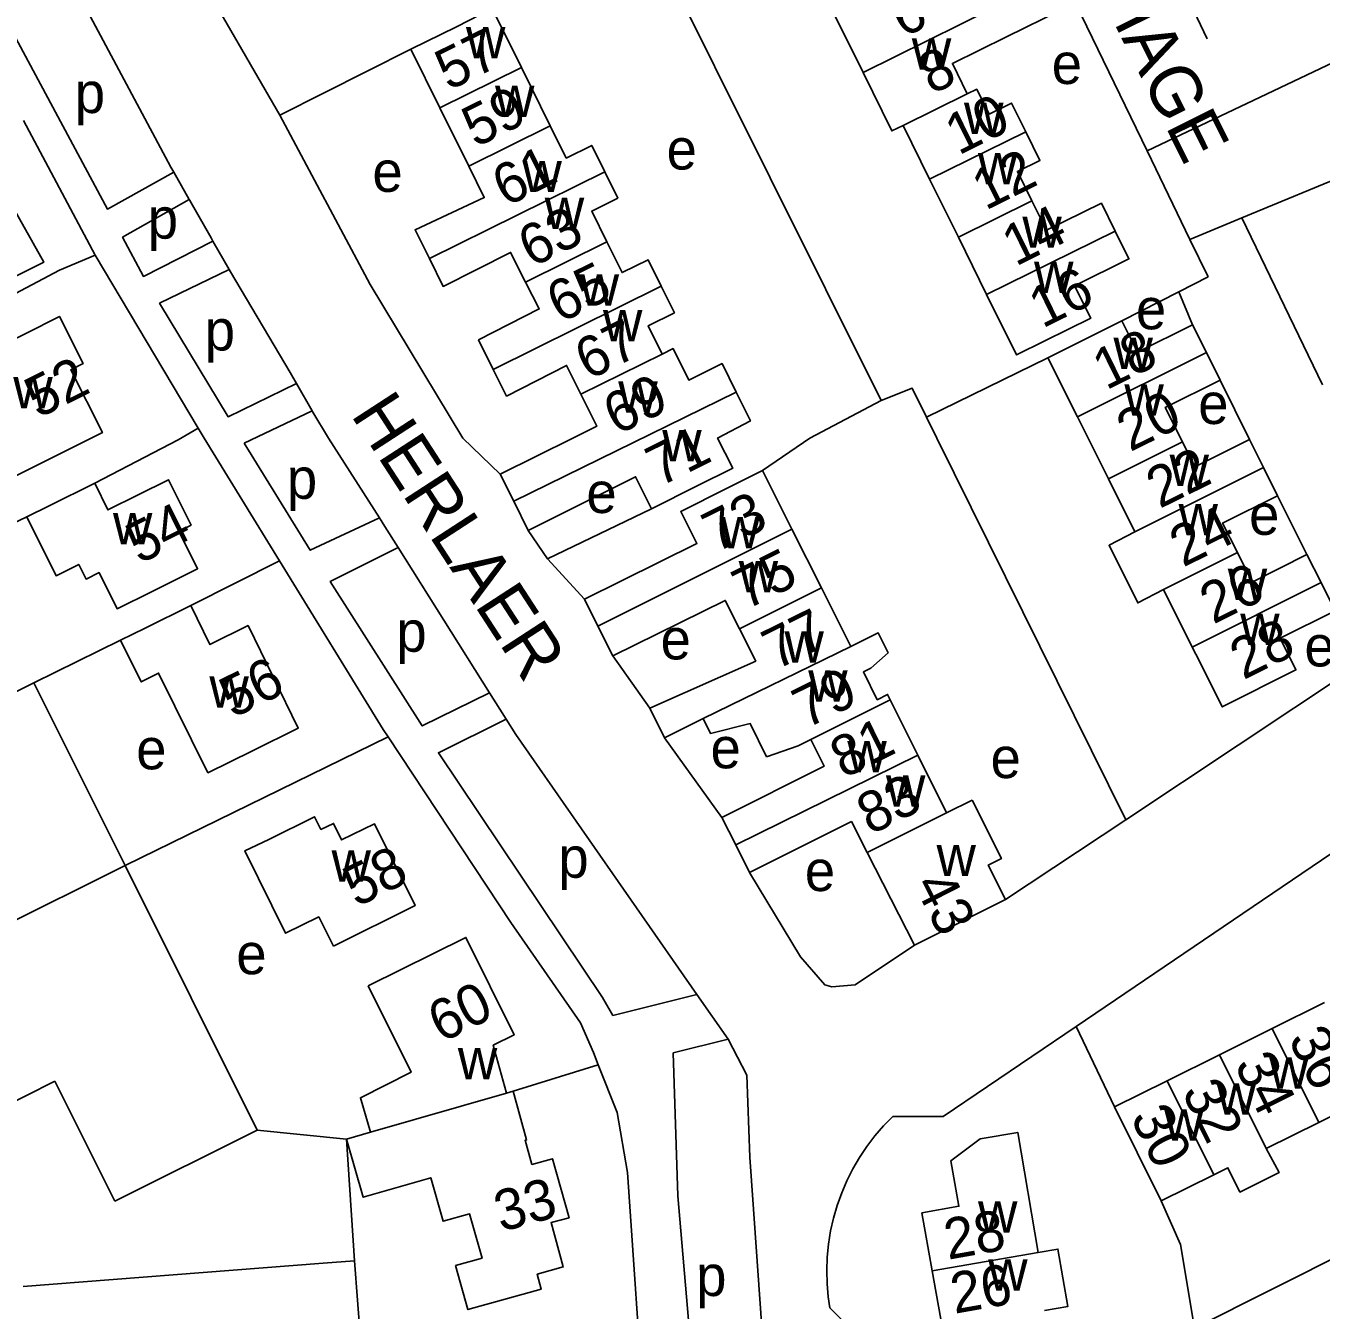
# Model space of a CAD drawing. Extents: x 157794 to 159375, y 380877 to 382306.
# Drawn here: x 158143.1 to 158270.1, y 381414.5 to 381540.4 of the extents above; entities that cross this region are included whole.
import ezdxf

# ---------------------------------------------------------------- set-up
doc = ezdxf.new("R2010")
doc.units = 0
for name, color, linetype in [('BLT_Basislijn', 7, 'Continuous'), ('BLT_Bebouwing', 7, 'Continuous'), ('BLT_Centroide', 7, 'Continuous'), ('BLT_Huisnummer', 7, 'Continuous'), ('BLT_Huisnummer_ tussenligend', 7, 'Continuous'), ('BLT_Onderverdeling_panden', 7, 'Continuous'), ('BLT_Straatnaam', 7, 'Continuous')]:
    doc.layers.add(name, color=color, linetype=linetype)

msp = doc.modelspace()

# ---------------------------------------------------------------- linework, layer by layer
at = {"layer": 'BLT_Basislijn'}
for p, q in [((158157.31, 381526.56), (158146.78, 381546.28)), ((158256.41, 381544.49), (158258.95, 381539.17)), ((158167.98, 381531.66), (158161.74, 381542.47)), ((158167.98, 381531.66), (158180.84, 381538.13)), ((158142.83, 381531.16), (158149.86, 381517.95)), ((158157.31, 381526.56), (158157.58, 381526.08)), ((158157.58, 381526.08), (158159.09, 381523.39)), ((158159.09, 381523.39), (158159.15, 381523.29)), ((158161.24, 381519.65), (158159.15, 381523.29)), ((158257.27, 381519.49), (158262.35, 381521.59)), ((158270.26, 381505.23), (158262.35, 381521.59)), ((158161.43, 381519.31), (158161.24, 381519.65)), ((158163.02, 381516.52), (158161.43, 381519.31)), ((158257.27, 381519.49), (158259.06, 381515.8)), ((158149.86, 381517.95), (158159.98, 381500.96)), ((158163.14, 381516.3), (158163.02, 381516.52)), ((158168.99, 381506.42), (158163.14, 381516.3)), ((158256.19, 381514.34), (158259.06, 381515.8)), ((158250.6, 381511.5), (158256.19, 381514.34)), ((158257.53, 381511.1), (158256.19, 381514.34)), ((158243.33, 381507.88), (158231.43, 381502.06)), ((158169.61, 381505.34), (158168.99, 381506.42)), ((158171.17, 381502.66), (158169.61, 381505.34)), ((158260.23, 381505.69), (158263.1, 381499.86)), ((158164.48, 381499.51), (158171.17, 381502.66)), ((158171.23, 381502.55), (158171.17, 381502.66)), ((158265.86, 381494.35), (158268.75, 381488.57)), ((158143.17, 381492.26), (158133.01, 381487.43)), ((158178.3, 381491.34), (158177.76, 381492.19)), ((158204.46, 381493.07), (158194.24, 381488.16)), ((158178.3, 381491.34), (158179.6, 381489.27)), ((158192.36, 381490.94), (158194.24, 381488.16)), ((158179.6, 381489.27), (158188.57, 381475.01)), ((158194.24, 381488.16), (158197.88, 381484.19)), ((158167.96, 381487.97), (158159.25, 381483.57)), ((158152.36, 381480.17), (158143.85, 381476)), ((158200.66, 381478.65), (158204.28, 381473.52)), ((158250.97, 381462.56), (158273.97, 381477.85)), ((158188.57, 381475.01), (158190.18, 381472.44)), ((158152.81, 381458.07), (158178.61, 381470.69)), ((158205.72, 381470.59), (158211.36, 381462.8)), ((158239.19, 381454.73), (158250.97, 381462.56)), ((158208.89, 381445.41), (158200.64, 381443.37)), ((158208.89, 381445.41), (158211.98, 381441.03)), ((158249.88, 381434.4), (158246.12, 381442.3)), ((158211.98, 381441.03), (158206.57, 381439.69)), ((158190.87, 381435.94), (158199.22, 381438.54)), ((158198.75, 381439.73), (158199.22, 381438.54)), ((158165.77, 381432.12), (158174.53, 381431.23)), ((158174.53, 381431.23), (158175.3, 381419.31)), ((158276.46, 381422.1), (158257.72, 381412.71))]:
    msp.add_line(p, q, dxfattribs=at)
for points in [[(158235.99, 381562.86), (158237.46, 381560.36), (158253.07, 381528.17)], [(158226.98, 381503.7), (158205.21, 381547.4), (158205.15, 381548.11)], [(158146.78, 381546.28), (158140.11, 381542.9), (158151.08, 381522.46), (158157.58, 381526.08)], [(158253.07, 381528.17), (158271.99, 381537.18), (158273.59, 381536.3), (158277.59, 381528.09)], [(158167.98, 381531.66), (158176.84, 381515.05), (158185.93, 381500), (158189.6, 381496.46)], [(158253.07, 381528.17), (158257.27, 381519.49)], [(158262.35, 381521.59), (158273.46, 381526.17), (158277.59, 381528.09)], [(158159.09, 381523.39), (158152.56, 381519.69), (158154.61, 381515.85), (158161.43, 381519.31)], [(158124.05, 381505.22), (158134.3, 381510.27), (158138.75, 381512.44), (158146.39, 381516.48), (158149.86, 381517.95)], [(158163.02, 381516.52), (158156.2, 381513.22), (158162.92, 381502.09), (158169.61, 381505.34)], [(158226.98, 381503.7), (158230.03, 381504.88), (158231.43, 381502.06)], [(158226.98, 381503.7), (158219.98, 381500), (158215.35, 381496.83)], [(158177.76, 381492.19), (158172.77, 381500), (158171.23, 381502.55)], [(158250.97, 381462.56), (158232.43, 381500), (158231.43, 381502.06)], [(158149.83, 381495.57), (158158.01, 381499.82), (158159.98, 381500.96)], [(158167.96, 381487.97), (158160.56, 381500), (158159.98, 381500.96)], [(158164.48, 381499.51), (158170.98, 381488.99), (158177.76, 381492.19)], [(158188.57, 381475.01), (158181.96, 381471.76), (158172.94, 381485.92), (158179.6, 381489.27)], [(158178.61, 381470.69), (158178.14, 381471.4), (158167.96, 381487.97)], [(158190.18, 381472.44), (158183.54, 381469.14), (158199.64, 381445.14), (158200.64, 381443.37)], [(158190.18, 381472.44), (158191.13, 381470.93), (158208.89, 381445.41)], [(158178.61, 381470.69), (158190.65, 381452.47), (158197.49, 381442.66), (158198.75, 381439.73)], [(158246.12, 381442.3), (158272.11, 381459.9)], [(158214.07, 381457.39), (158219.05, 381449.13), (158221.44, 381446.36), (158222.14, 381446.16), (158224.42, 381446.38), (158230.24, 381450.25)], [(158228.12, 381433.47), (158233.07, 381433.47), (158246.12, 381442.3)], [(158211.98, 381441.03), (158213.8, 381437.52), (158214.09, 381429.48)], [(158199.22, 381438.54), (158201.07, 381433.86), (158202.1, 381427.97), (158203.77, 381403.69), (158203.9, 381401.89)], [(158219.17, 381336.49), (158214.67, 381336.49), (158207.04, 381425.67), (158206.57, 381439.69)], [(158228.12, 381433.47), (158227.22, 381432.54), (158226.37, 381431.56), (158225.58, 381430.52), (158224.86, 381429.44), (158224.2, 381428.32), (158223.62, 381427.16), (158223.11, 381425.97), (158222.67, 381424.74), (158222.31, 381423.49), (158222.02, 381422.23), (158221.82, 381420.94), (158221.69, 381419.65), (158221.65, 381418.35), (158221.68, 381417.05), (158221.79, 381415.76), (158221.95, 381414.68)], [(158219.17, 381336.49), (158213.66, 381407.79), (158213.61, 381409.17), (158215.34, 381411.84), (158214.09, 381429.48)], [(158254.46, 381425.19), (158256.35, 381420.9), (158257.72, 381412.71)], [(158221.95, 381414.68), (158224.91, 381411.72), (158227.38, 381378.6), (158225.41, 381376.62), (158225.44, 381376.15)]]:
    msp.add_lwpolyline(points, dxfattribs=at)
at = {"layer": 'BLT_Bebouwing'}
for p, q in [((158188.83, 381542.12), (158191.68, 381536.36)), ((158225.2, 381535.87), (158222.38, 381541.57)), ((158183.68, 381532.4), (158180.84, 381538.13)), ((158191.68, 381536.36), (158194.52, 381530.62)), ((158186.52, 381526.66), (158183.68, 381532.4)), ((158231.73, 381525.39), (158229.13, 381530.66)), ((158234.55, 381519.69), (158231.73, 381525.39)), ((158237.32, 381514.07), (158234.55, 381519.69)), ((158257.53, 381511.1), (158258.88, 381508.39)), ((158260.23, 381505.69), (158258.88, 381508.39)), ((158243.33, 381507.88), (158246.23, 381502.08)), ((158264.48, 381497.1), (158263.1, 381499.86)), ((158265.86, 381494.35), (158264.48, 381497.1)), ((158190.93, 381493.81), (158189.6, 381496.46)), ((158218.23, 381491.07), (158215.35, 381496.83)), ((158249.27, 381495.99), (158251.86, 381490.79)), ((158192.36, 381490.94), (158190.93, 381493.81)), ((158221.11, 381485.32), (158218.23, 381491.07)), ((158270.13, 381485.82), (158268.75, 381488.57)), ((158271.51, 381483.07), (158270.13, 381485.82)), ((158223.99, 381479.57), (158221.11, 381485.32)), ((158254.68, 381485.15), (158257.5, 381479.5)), ((158143.85, 381476), (158138.55, 381473.36)), ((158152.81, 381458.07), (158143.85, 381476)), ((158230.58, 381468.89), (158233.39, 381463.23)), ((158233.39, 381463.23), (158235.91, 381464.49)), ((158211.36, 381462.8), (158212.72, 381460.09)), ((158212.72, 381460.09), (158214.07, 381457.39)), ((158225.61, 381459.34), (158230.24, 381450.25)), ((158165.77, 381432.12), (158152.81, 381458.07)), ((158230.24, 381450.25), (158239.19, 381454.73)), ((158265.33, 381442.08), (158270.48, 381444.64)), ((158260.18, 381439.52), (158265.33, 381442.08)), ((158255.03, 381436.96), (158260.18, 381439.52)), ((158124.88, 381426.41), (158145.93, 381436.91)), ((158145.93, 381436.91), (158151.8, 381425.14)), ((158249.88, 381434.4), (158255.03, 381436.96)), ((158269.91, 381432.87), (158275.06, 381435.43)), ((158264.76, 381430.31), (158269.91, 381432.87)), ((158254.46, 381425.19), (158259.61, 381427.75)), ((158175.3, 381419.31), (158176.41, 381405.43)), ((158231.98, 381418.33), (158232.99, 381412.65))]:
    msp.add_line(p, q, dxfattribs=at)
for points in [[(158235.43, 381533.77), (158233.96, 381536.74), (158239.28, 381539.37), (158244.73, 381542.05), (158243.31, 381544.94), (158237.9, 381542.15)], [(158180.84, 381538.13), (158185.32, 381540.35), (158188.83, 381542.12)], [(158229.13, 381530.66), (158228.04, 381530.12), (158225.2, 381535.87)], [(158241.16, 381530.04), (158239.77, 381532.86), (158237.57, 381531.77), (158236.35, 381534.22), (158235.43, 381533.77)], [(158194.52, 381530.62), (158196.09, 381527.46), (158198.58, 381528.7), (158199.86, 381526.12)], [(158241.77, 381523.26), (158240.35, 381526.15), (158242.55, 381527.23), (158241.16, 381530.04)], [(158120.7, 381511.97), (158132.42, 381517.74), (158135, 381512.35), (158144.83, 381517.25), (158141.41, 381523.37), (158138.96, 381523.38), (158136.7, 381527.99)], [(158182.66, 381517.6), (158181.25, 381520.43), (158188.04, 381523.59), (158186.52, 381526.66)], [(158199.86, 381526.12), (158201.13, 381523.54), (158198.58, 381522.27), (158200.08, 381519.25)], [(158249.93, 381520.31), (158248.58, 381523.04), (158243.2, 381520.38), (158241.77, 381523.26)], [(158249.93, 381520.31), (158251.28, 381517.58), (158245.96, 381514.94), (158247.53, 381511.75), (158243.05, 381509.53), (158240.25, 381508.15), (158237.32, 381514.07)], [(158200.08, 381519.25), (158201.57, 381516.23), (158204.11, 381517.49), (158205.4, 381514.89)], [(158192.08, 381515.29), (158190.63, 381518.21), (158184.01, 381514.87), (158182.66, 381517.6)], [(158188.93, 381506.72), (158187.48, 381509.63), (158193.43, 381512.67), (158192.08, 381515.29)], [(158205.4, 381514.89), (158206.69, 381512.29), (158204.11, 381511), (158205.48, 381508.24)], [(158149.49, 381500), (158145.43, 381497.97), (158141.58, 381496.05), (158139.58, 381500), (158138.06, 381502.99), (158136.36, 381502.13), (158133.12, 381508.57), (158133.82, 381508.92), (158138.28, 381511.17), (158139.61, 381508.53), (158146.37, 381511.93), (158148.69, 381507.31), (158147.48, 381506.7), (158150.58, 381500.54), (158149.49, 381500)], [(158250.6, 381511.5), (158246.09, 381509.25), (158243.33, 381507.88)], [(158250.6, 381511.5), (158252.14, 381508.41), (158257.53, 381511.1)], [(158205.48, 381508.24), (158206.56, 381508.78), (158208.1, 381505.68), (158211.38, 381507.3), (158212.77, 381504.5)], [(158197.52, 381504.3), (158196.12, 381507.12), (158190.23, 381504.12), (158188.93, 381506.72)], [(158256.54, 381499.62), (158256.35, 381500), (158255.91, 381500.87), (158254.85, 381503.01), (158260.23, 381505.69)], [(158189.6, 381496.46), (158196.73, 381500), (158199.08, 381501.16), (158197.52, 381504.3)], [(158212.77, 381504.5), (158214.16, 381501.69), (158210.93, 381500), (158212.43, 381497.06), (158208.93, 381495.3), (158204.46, 381493.07)], [(158246.23, 381502.08), (158247.27, 381500), (158249.27, 381495.99)], [(158263.1, 381499.86), (158257.75, 381497.18), (158256.54, 381499.62)], [(158149.83, 381495.57), (158151.13, 381492.96), (158157.07, 381495.91), (158159.28, 381491.47), (158158.09, 381490.88), (158159.92, 381487.19), (158155.45, 381484.96), (158152.03, 381483.26), (158150.26, 381486.81), (158148.98, 381486.17), (158148.26, 381487.61), (158146.04, 381486.5), (158143.17, 381492.26)], [(158204.46, 381493.07), (158202.89, 381496.21), (158192.36, 381490.94)], [(158215.35, 381496.83), (158211.79, 381495.05), (158207.32, 381492.81), (158208.9, 381489.66), (158197.88, 381484.19)], [(158143.17, 381492.26), (158145.36, 381493.35), (158149.83, 381495.57)], [(158261.92, 381488.77), (158260.47, 381491.66), (158265.86, 381494.35)], [(158251.86, 381490.79), (158249.33, 381489.48), (158252.15, 381483.83), (158254.68, 381485.15)], [(158268.75, 381488.57), (158263.36, 381485.88), (158261.92, 381488.77)], [(158152.36, 381480.17), (158154.77, 381481.36), (158159.25, 381483.57)], [(158159.25, 381483.57), (158161.13, 381479.75), (158164.88, 381481.61), (158169.8, 381471.55), (158165.32, 381469.33), (158160.94, 381467.18), (158156.1, 381476.95), (158154.39, 381476.08), (158152.36, 381480.17)], [(158197.88, 381484.19), (158199.2, 381481.55)], [(158200.66, 381478.65), (158211.69, 381484.08), (158213.08, 381481.3)], [(158257.5, 381479.5), (158258.2, 381478.11), (158260.43, 381473.63), (158267.67, 381477.26), (158266.11, 381480.37), (158271.51, 381483.07)], [(158199.2, 381481.55), (158200.66, 381478.65)], [(158213.08, 381481.3), (158214.67, 381478.13), (158204.28, 381473.52)], [(158227.87, 381474.32), (158227.6, 381474.85), (158226.6, 381474.34), (158225.24, 381477.06), (158225.98, 381477.44), (158227.66, 381478.93), (158226.67, 381480.91), (158223.99, 381479.57)], [(158227.87, 381474.32), (158230.58, 381468.89)], [(158204.28, 381473.52), (158205.72, 381470.59)], [(158205.72, 381470.59), (158209.53, 381472.48)], [(158209.53, 381472.48), (158210.23, 381471.03), (158214.13, 381471.99), (158215.72, 381468.72)], [(158220.08, 381470.42), (158221.38, 381467.81), (158211.36, 381462.8)], [(158215.72, 381468.72), (158218.83, 381469.8), (158220.08, 381470.42)], [(158239.19, 381454.73), (158237.49, 381458.11), (158238.78, 381458.76), (158235.91, 381464.49)], [(158173.25, 381450.17), (158181.26, 381454.14), (158177.27, 381462.17), (158174.05, 381460.58), (158173.26, 381462.21), (158172.02, 381461.61), (158171.39, 381462.85), (158166.9, 381460.63), (158164.57, 381459.52), (158168.53, 381451.43), (158171.8, 381453.03), (158173.25, 381450.17)], [(158214.07, 381457.39), (158224.06, 381462.38), (158225.61, 381459.34)], [(158176.66, 381446.28), (158186.25, 381451.02), (158190.97, 381441.46), (158188.93, 381440.44), (158190.23, 381435.74), (158190.87, 381435.94)], [(158176.89, 381431.91), (158175.89, 381435.29), (158180.86, 381437.79), (158176.66, 381446.28)], [(158190.87, 381435.94), (158192.2, 381431.16), (158192.04, 381431.12), (158192.72, 381428.75), (158194.74, 381429.31), (158196.36, 381423.53), (158194.59, 381423.05), (158195.79, 381418.71), (158193.24, 381417.99), (158193.64, 381416.52), (158186.44, 381414.52), (158185.23, 381418.83)], [(158254.46, 381425.19), (158252.1, 381429.93), (158249.88, 381434.4)], [(158151.8, 381425.14), (158165.77, 381432.12)], [(158174.53, 381431.23), (158176.89, 381431.91)], [(158185.23, 381418.83), (158187.83, 381419.56), (158186.61, 381423.91), (158184, 381423.18), (158182.8, 381427.45), (158176.17, 381425.54), (158174.53, 381431.23)], [(158242.39, 381420.11), (158240.37, 381431.9), (158236.69, 381431.28), (158233.82, 381429.11), (158234.61, 381424.65), (158230.97, 381424), (158231.98, 381418.33)], [(158259.61, 381427.75), (158260.99, 381428.43), (158262.17, 381426.05), (158266.01, 381427.96), (158264.76, 381430.31)], [(158242.99, 381414.42), (158245.3, 381414.83), (158244.31, 381420.45), (158242.39, 381420.11)], [(158172.23, 381419.07), (158175.3, 381419.31)]]:
    msp.add_lwpolyline(points, dxfattribs=at)
at = {"layer": 'BLT_Onderverdeling_panden'}
for p, q in [((158237.9, 381542.15), (158225.2, 381535.87)), ((158183.68, 381532.4), (158191.68, 381536.36)), ((158235.43, 381533.77), (158229.13, 381530.66)), ((158186.52, 381526.66), (158194.52, 381530.62)), ((158241.16, 381530.04), (158231.73, 381525.39)), ((158199.86, 381526.12), (158182.66, 381517.6)), ((158241.77, 381523.26), (158234.55, 381519.69)), ((158249.93, 381520.31), (158237.32, 381514.07)), ((158200.08, 381519.25), (158192.08, 381515.29)), ((158205.4, 381514.89), (158188.93, 381506.72)), ((158258.88, 381508.39), (158246.23, 381502.08)), ((158205.48, 381508.24), (158197.52, 381504.3)), ((158212.77, 381504.5), (158190.93, 381493.81)), ((158256.54, 381499.62), (158249.27, 381495.99)), ((158264.48, 381497.1), (158251.86, 381490.79)), ((158199.2, 381481.55), (158218.23, 381491.07)), ((158261.92, 381488.77), (158254.68, 381485.15)), ((158270.13, 381485.82), (158257.5, 381479.5)), ((158213.08, 381481.3), (158221.11, 381485.32)), ((158209.53, 381472.48), (158223.99, 381479.57)), ((158220.08, 381470.42), (158227.87, 381474.32)), ((158212.72, 381460.09), (158230.58, 381468.89)), ((158225.61, 381459.34), (158233.39, 381463.23)), ((158138.84, 381451.11), (158152.81, 381458.07)), ((158269.91, 381432.87), (158265.33, 381442.08)), ((158264.76, 381430.31), (158260.18, 381439.52)), ((158259.61, 381427.75), (158255.03, 381436.96)), ((158176.89, 381431.91), (158190.23, 381435.74)), ((158231.98, 381418.33), (158242.39, 381420.11))]:
    msp.add_line(p, q, dxfattribs=at)
msp.add_lwpolyline([(158142.81, 381416.78), (158172.23, 381419.07)], dxfattribs=at)

# ---------------------------------------------------------------- texts
at = {"layer": 'BLT_Centroide'}
for s, p in [('w', (158186.25, 381537.25)), ('w', (158229.99, 381536.12)), ('e', (158243.71, 381534.73)), ('p', (158147.87, 381531.88)), ('w', (158189.1, 381531.5)), ('w', (158235.11, 381529.81)), ('e', (158205.93, 381526.34)), ('w', (158236.48, 381524.88)), ('e', (158177.07, 381524.15)), ('w', (158191.79, 381524.12)), ('p', (158155.03, 381519.56)), ('w', (158193.98, 381520.5)), ('w', (158240.83, 381518.66)), ('w', (158241.98, 381514.22)), ('w', (158197.41, 381513)), ('e', (158251.97, 381510.67)), ('w', (158199.69, 381509.5)), ('p', (158160.62, 381508.59)), ('w', (158249.77, 381506.78)), ('w', (158141.84, 381502.92)), ('w', (158201.19, 381502.48)), ('w', (158250.84, 381502.19)), ('e', (158258.08, 381501.38)), ('w', (158205.5, 381497.72)), ('w', (158255.27, 381495.31)), ('p', (158168.68, 381494.04)), ('e', (158198.06, 381492.65)), ('w', (158256.15, 381490.47)), ('e', (158263.07, 381490.51)), ('w', (158151.62, 381489.59)), ('w', (158211.21, 381489.19)), ('w', (158213, 381484.88)), ('w', (158260.98, 381484.12)), ('p', (158179.42, 381479.04)), ('w', (158262.2, 381479.72)), ('e', (158205.34, 381478.29)), ('w', (158217.49, 381477.97)), ('e', (158268.5, 381477.6)), ('w', (158161.08, 381473.55)), ('w', (158219.82, 381474.16)), ('e', (158153.9, 381467.51)), ('e', (158210.24, 381467.61)), ('w', (158223.66, 381467.22)), ('e', (158237.71, 381466.65)), ('w', (158227.45, 381463.84)), ('w', (158232.41, 381457.03)), ('w', (158173.06, 381456.5)), ('p', (158195.31, 381456.87)), ('e', (158219.49, 381455.57)), ('e', (158163.72, 381447.41)), ('w', (158185.45, 381437.11)), ('w', (158265.05, 381436.19)), ('w', (158259.89, 381433.64)), ('w', (158254.75, 381431.08)), ('w', (158236.48, 381422.06)), ('w', (158237.48, 381416.38)), ('p', (158208.83, 381415.85))]:
    msp.add_text(s, height=4, dxfattribs=at).set_placement(p)
at = {"layer": 'BLT_Huisnummer'}
for s, rotation, p in [('6', 26.2949, (158229.15, 381539.23)), ('57', 26.3501, (158184.55, 381534.03)), ('10', 26.2949, (158234.57, 381527.7)), ('61', 26.3501, (158190.15, 381522.64)), ('14', 26.2949, (158240.16, 381516.8)), ('65', 26.3501, (158195.49, 381511.23)), ('18', 26.2949, (158249.04, 381504.66)), ('52', 26.5312, (158144.28, 381501.89)), ('69', 26.3501, (158201.05, 381500.24)), ('22', 26.2949, (158254.3, 381493.04)), ('73', 26.3501, (158210.76, 381488.7)), ('54', 26.4677, (158154.21, 381487.6)), ('77', 26.3501, (158216.65, 381477.2)), ('28', 26.2949, (158262.51, 381476.25)), ('56', 26.0982, (158163.37, 381472.48)), ('83', 26.3501, (158225.91, 381461.03)), ('58', 26.3586, (158175.51, 381453.94)), ('43', 297.0355, (158230.13, 381456.19)), ('60', 26.3206, (158183.84, 381440.64)), ('34', 296.4394, (158261.57, 381438.55)), ('30', 296.4394, (158251.38, 381433.38)), ('33', 15.4709, (158189.69, 381422.11)), ('28', 10.0622, (158233.53, 381419.4)), ('26', 10.0622, (158234.17, 381414.1))]:
    msp.add_text(s, height=4, rotation=rotation, dxfattribs=at).set_placement(p)
at = {"layer": 'BLT_Huisnummer_ tussenligend'}
for s, rotation, p in [('8', 26.2949, (158231.94, 381533.65)), ('59', 26.3501, (158187.18, 381528.45)), ('12', 26.2949, (158237.21, 381522.29)), ('63', 26.3501, (158192.7, 381516.69)), ('16', 26.2949, (158242.79, 381510.72)), ('67', 26.3501, (158198.26, 381505.63)), ('20', 26.2949, (158251.4, 381498.61)), ('71', 26.3501, (158205.24, 381495.18)), ('24', 26.2949, (158256.59, 381487.29)), ('75', 26.3501, (158213.71, 381483.11)), ('26', 26.2949, (158259.55, 381481.7)), ('79', 26.3501, (158219.61, 381471.45)), ('81', 26.3501, (158223.3, 381466.56)), ('36', 296.4394, (158266.86, 381441.07)), ('32', 296.4394, (158256.42, 381435.88))]:
    msp.add_text(s, height=4, rotation=rotation, dxfattribs=at).set_placement(p)
at = {"layer": 'BLT_Straatnaam'}
for s, rotation, p in [('HENKENSHAGE', 296.4188, (158233.99, 381572.53)), ('HERLAER', 303.0111, (158174.88, 381502.3))]:
    msp.add_text(s, height=5, rotation=rotation, dxfattribs=at).set_placement(p)

doc.saveas('drawing.dxf')
